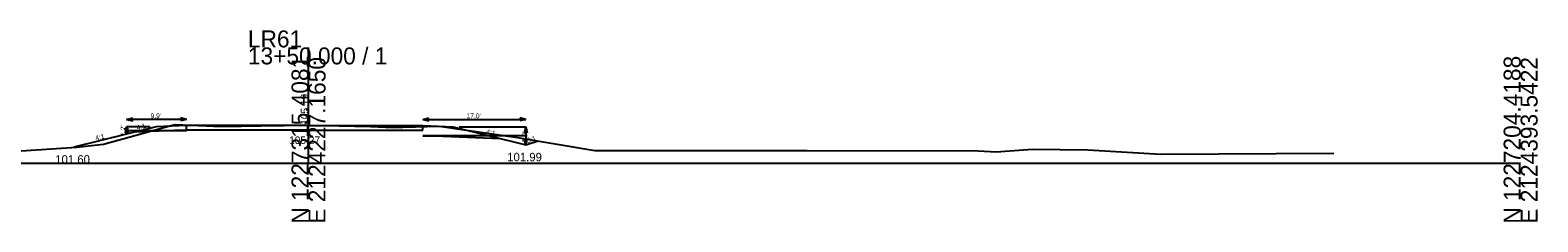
# Model space of a CAD drawing. Extents: x -26 to 1403, y -10 to 9574.
# Drawn here: x 1154.1 to 1402.8, y 3490.3 to 3521.9 of the extents above; entities that cross this region are included whole.
import ezdxf

# ---------------------------------------------------------------- set-up
doc = ezdxf.new("R2010")
doc.units = 0
for name, color, linetype in [('XS_CELL', 7, 'Continuous'), ('XS_P_FINISHED_GRADE', 7, 'Continuous'), ('XS_P_FINISHED_GRADE_ELEV_TX', 7, 'Continuous'), ('XS_P_SUBGRADE_GRANULAR', 7, 'Continuous'), ('XS_P_SUBGRADE_PAVEMENT', 7, 'Continuous'), ('XS_P_TX_CLEARZONE', 7, 'Continuous'), ('XS_P_TX_DCH', 7, 'Continuous'), ('XS_P_TX_FS_BS', 7, 'Continuous'), ('XS_X_GROUND', 7, 'Continuous'), ('XS_X_GROUND_TX', 7, 'Continuous')]:
    doc.layers.add(name, color=color, linetype=linetype)

msp = doc.modelspace()

# ---------------------------------------------------------------- linework, layer by layer
at = {"layer": 'XS_CELL'}
for p, q in [((1200, 3500), (1200, 3519.07)), ((1000, 3500), (1200, 3500)), ((1200, 3500), (1400, 3500))]:
    msp.add_line(p, q, dxfattribs=at)
at = {"layer": 'XS_P_FINISHED_GRADE'}
for p, q in [((1174.86, 3505.99), (1169.99, 3504.77)), ((1179.88, 3506.19), (1174.86, 3505.99)), ((1200, 3506.19), (1179.88, 3506.19)), ((1200, 3506.19), (1218.85, 3506.19)), ((1218.85, 3506.19), (1223.85, 3505.99)), ((1223.85, 3505.99), (1235.85, 3502.99)), ((1169.99, 3504.77), (1161.27, 3502.6)), ((1235.85, 3502.99), (1237.87, 3503.66))]:
    msp.add_line(p, q, dxfattribs=at)
at = {"layer": 'XS_P_SUBGRADE_GRANULAR'}
for p, q in [((1169.79, 3505.38), (1179.88, 3505.38)), ((1177.88, 3505.38), (1171.39, 3505.12)), ((1179.88, 3505.38), (1177.88, 3505.38)), ((1236.05, 3504.49), (1218.85, 3504.49)), ((1218.85, 3504.49), (1220.85, 3504.49)), ((1220.85, 3504.49), (1231.57, 3504.06))]:
    msp.add_line(p, q, dxfattribs=at)
at = {"layer": 'XS_P_SUBGRADE_PAVEMENT'}
for p, q in [((1179.88, 3505.44), (1179.88, 3506.19)), ((1200, 3505.44), (1179.88, 3505.44)), ((1200, 3505.44), (1218.85, 3505.44)), ((1218.85, 3505.44), (1218.85, 3506.19))]:
    msp.add_line(p, q, dxfattribs=at)
at = {"layer": 'XS_P_TX_CLEARZONE'}
for p, q in [((1169.99, 3505.99), (1169.74, 3504.99)), ((1169.99, 3504.77), (1169.74, 3505.77)), ((1169.99, 3507.19), (1170.99, 3507.44)), ((1169.99, 3507.19), (1170.99, 3506.94)), ((1179.88, 3507.19), (1169.99, 3507.19)), ((1169.99, 3505.99), (1170.24, 3504.99)), ((1169.99, 3505.99), (1169.99, 3504.77)), ((1173.86, 3505.99), (1169.99, 3505.99)), ((1169.99, 3504.77), (1170.24, 3505.77)), ((1179.88, 3507.19), (1178.87, 3507.44)), ((1179.88, 3507.19), (1178.87, 3506.94)), ((1218.85, 3507.19), (1219.85, 3507.44)), ((1218.85, 3507.19), (1219.85, 3506.94)), ((1218.85, 3507.19), (1235.85, 3507.19)), ((1224.85, 3505.99), (1235.85, 3505.99)), ((1235.85, 3507.19), (1234.85, 3507.44)), ((1235.85, 3507.19), (1234.85, 3506.94)), ((1235.85, 3505.99), (1235.6, 3504.99)), ((1235.85, 3505.99), (1235.85, 3502.99)), ((1235.85, 3505.99), (1236.1, 3504.99)), ((1235.85, 3502.99), (1235.6, 3503.99)), ((1235.85, 3502.99), (1236.1, 3503.99))]:
    msp.add_line(p, q, dxfattribs=at)
at = {"layer": 'XS_X_GROUND'}
for p, q in [((1166.16, 3503.11), (1177.1, 3506.13)), ((1177.1, 3506.13), (1177.98, 3506.36)), ((1177.98, 3506.36), (1185.64, 3506.02)), ((1185.64, 3506.02), (1192.18, 3506.15)), ((1192.18, 3506.15), (1199.85, 3506.27)), ((1199.85, 3506.27), (1210.23, 3506.04)), ((1210.23, 3506.04), (1213.98, 3505.89)), ((1213.98, 3505.89), (1217.21, 3505.99)), ((1217.21, 3505.99), (1217.63, 3506)), ((1217.63, 3506), (1221.55, 3506.09)), ((1221.55, 3506.09), (1234.47, 3504.24)), ((1161.72, 3502.63), (1166.16, 3503.11)), ((1234.47, 3504.24), (1247.23, 3502.05)), ((1147.49, 3501.67), (1161.72, 3502.63)), ((1247.23, 3502.05), (1282.3, 3502.05)), ((1282.3, 3502.05), (1310.49, 3502.03)), ((1310.49, 3502.03), (1313.45, 3501.83)), ((1313.45, 3501.83), (1319.45, 3502.29)), ((1319.45, 3502.29), (1328.6, 3502.18)), ((1328.6, 3502.18), (1340.63, 3501.47)), ((1340.63, 3501.47), (1369.19, 3501.63))]:
    msp.add_line(p, q, dxfattribs=at)

# ---------------------------------------------------------------- texts
at = {"layer": 'XS_CELL'}
for s, p in [('LR61', (1190, 3519.07)), ('13+50.000 / 1', (1190, 3516.27))]:
    msp.add_text(s, height=2.8, dxfattribs=at).set_placement(p)
for s, p in [('N 1227315.4081', (1200, 3490)), ('E 2124227.1650', (1202.8, 3490)), ('N 1227204.4188', (1400, 3490)), ('E 2124393.5422', (1402.8, 3490))]:
    msp.add_text(s, height=2.8, rotation=90, dxfattribs=at).set_placement(p)
at = {"layer": 'XS_P_FINISHED_GRADE_ELEV_TX'}
msp.add_text('105.19', height=1.25, rotation=90, dxfattribs=at).set_placement((1199.97, 3506.31))
at = {"layer": 'XS_P_TX_CLEARZONE'}
for s, p in [("9.9'", (1173.93, 3507.39)), ("17.0'", (1226.07, 3507.39))]:
    msp.add_text(s, height=0.8, dxfattribs=at).set_placement(p)
for s, p in [("1.2'", (1169.79, 3504.48)), ("3.0'", (1236.05, 3503.46))]:
    msp.add_text(s, height=0.8, rotation=90, dxfattribs=at).set_placement(p)
at = {"layer": 'XS_P_TX_DCH'}
for s, p in [('101.60', (1158.21, 3499.9)), ('101.99', (1232.78, 3500.29))]:
    msp.add_text(s, height=1.4, dxfattribs=at).set_placement(p)
at = {"layer": 'XS_P_TX_FS_BS'}
for s, rotation, p in [('4:1', 14.0035, (1171.72, 3505.41)), ('4:1', 345.9638, (1229.24, 3504.85)), ('4:1', 14.0035, (1164.92, 3503.71)), ('3:1', 18.4349, (1236.15, 3503.3))]:
    msp.add_text(s, height=0.8, rotation=rotation, dxfattribs=at).set_placement(p)
at = {"layer": 'XS_X_GROUND_TX'}
msp.add_text('105.27', height=1.25, rotation=360, dxfattribs=at).set_placement((1196.79, 3503.14))

doc.saveas('drawing.dxf')
